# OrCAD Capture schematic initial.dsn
size A
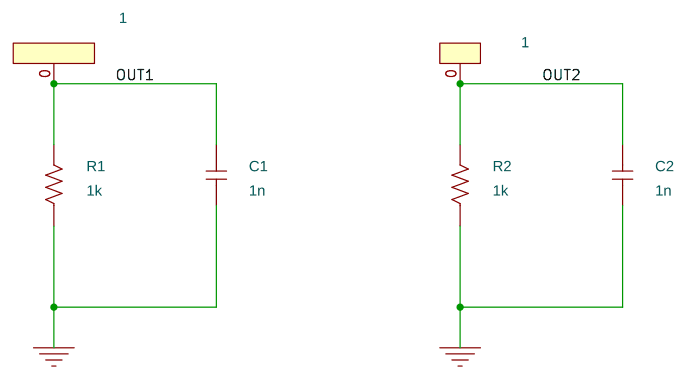
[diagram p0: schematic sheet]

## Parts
C1  1n  [cap196]
C2  1n  [cap196]
IC1  1
NS1  1
R1  1k  [AXRC05]
R2  1k  [AXRC05]

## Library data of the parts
C1 C2 = C
IC1 = IC1
NS1 = NODESET1
R1 R2 = R

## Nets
0: C1.1 C2.1 R1.1 R2.1
OUT1: C1.2 NS1.0(+) R1.2
OUT2: C2.2 IC1.0(+) R2.2
